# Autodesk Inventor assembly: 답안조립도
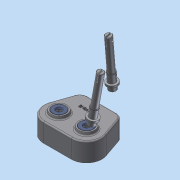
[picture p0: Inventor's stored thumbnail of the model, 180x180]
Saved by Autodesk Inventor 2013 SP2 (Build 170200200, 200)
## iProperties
Created: 2014-12
Part Number: 답안조립도
Document SubType Name: Assembly
Designer: dgall
Author: dgall
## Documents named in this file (9)
- C:\Documents and Settings\dgall\바탕 화면\441208V1042\답안조립도.iam
- C:\Documents and Settings\dgall\바탕 화면\441208V1042\본체.ipt
- C:\Documents and Settings\dgall\바탕 화면\441208V1042\오일시일-D-15.ipt
- C:\Documents and Settings\dgall\바탕 화면\441208V1042\커버.ipt
- C:\Documents and Settings\dgall\바탕 화면\441208V1042\베어링- 6203.ipt
- C:\Documents and Settings\dgall\바탕 화면\441208V1042\오일시일-D-17.ipt
- C:\Documents and Settings\dgall\바탕 화면\441208V1042\베어링- 6202.ipt
- C:\Documents and Settings\dgall\바탕 화면\441208V1042\서브축.ipt
- C:\Documents and Settings\dgall\바탕 화면\441208V1042\키5x5.ipt
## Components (6 placed, 4 different names)
1. KS B 2804 D D - 15 30 7:1
2. KS B 2804 D D - 15 30 7:2
3. KS B 2023 6203 - 17 x 40 x 12:1
4. KS B 2804 D D - 17 30 8:1
5. KS B 2023 6202 - 15 x 35 x 11:1
6. KS B 2023 6202 - 15 x 35 x 11:2
